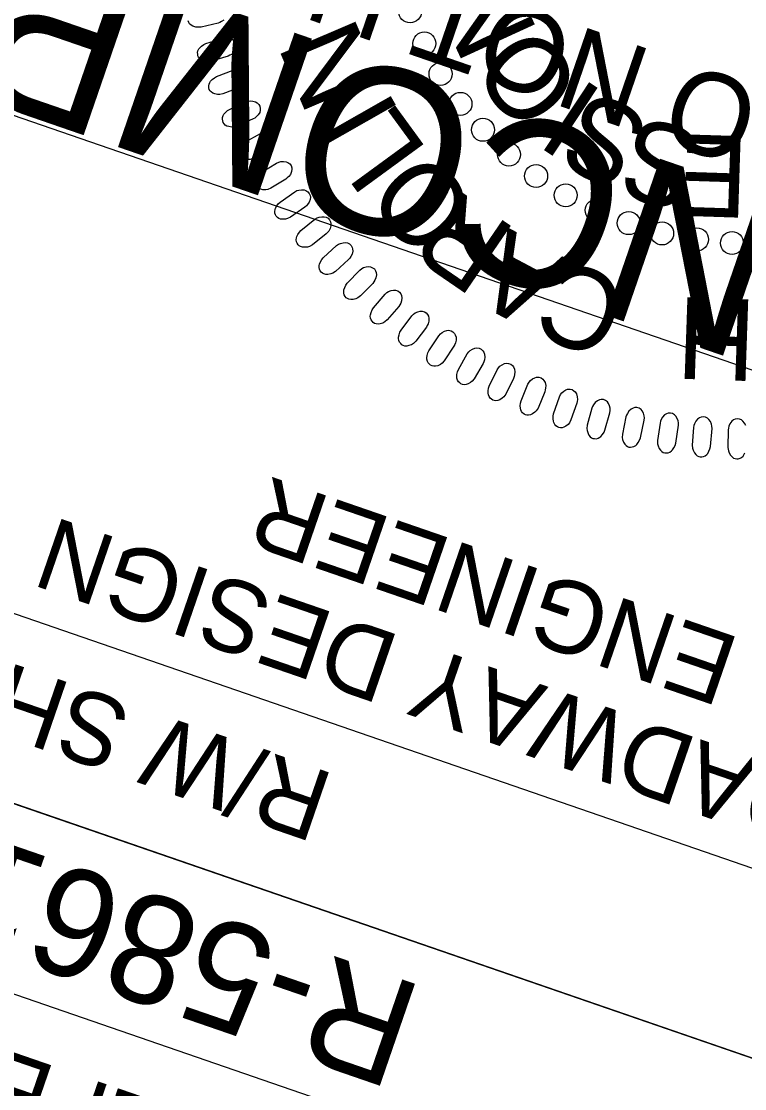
# Model space of a CAD drawing. Extents: x 479650 to 481768, y 492454 to 494037.
# Drawn here: x 479798.2 to 479848.6, y 492981.7 to 493055.9 of the extents above; entities that cross this region are included whole.
import ezdxf

# ---------------------------------------------------------------- set-up
doc = ezdxf.new("R2010")
doc.units = 0
for name, color, linetype in [('Sheet Data Field CELL', 7, 'Continuous'), ('Sheet PE Seal Cell', 7, 'Continuous'), ('Sheet Plan CELL', 7, 'Continuous'), ('Sheet Sticker Incomplete CELL', 7, 'Continuous')]:
    doc.layers.add(name, color=color, linetype=linetype)

msp = doc.modelspace()

# ---------------------------------------------------------------- linework, layer by layer
at = {"layer": 'Sheet PE Seal Cell'}
for points in [[(479812.334, 493055.999), (479812.174, 493055.892), (479812.055, 493055.833), (479811.933, 493055.789), (479810.739, 493055.505), (479810.517, 493055.49), (479810.369, 493055.509), (479810.178, 493055.578), (479810.049, 493055.648), (479809.946, 493055.738), (479809.882, 493055.831), (479809.837, 493055.935)], [(479848.654, 493027.806), (479848.568, 493027.968), (479848.458, 493028.109), (479848.362, 493028.191), (479848.206, 493028.253), (479848.057, 493028.276), (479847.907, 493028.239), (479847.801, 493028.191), (479847.673, 493028.094), (479847.55, 493027.926), (479847.48, 493027.748), (479847.447, 493027.619), (479847.43, 493027.489), (479847.408, 493026.263), (479847.441, 493026.043), (479847.491, 493025.903), (479847.6, 493025.731), (479847.695, 493025.619), (479847.806, 493025.538), (479847.91, 493025.496), (479848.022, 493025.474), (479848.135, 493025.491), (479848.254, 493025.52), (479848.36, 493025.577), (479848.467, 493025.675), (479848.528, 493025.754), (479848.598, 493025.902)]]:
    msp.add_lwpolyline(points, dxfattribs=at)
for points in [[(479812.623, 493053.492), (479811.45, 493053.135), (479811.229, 493053.106), (479811.08, 493053.115), (479810.885, 493053.173), (479810.752, 493053.234), (479810.643, 493053.318), (479810.574, 493053.406), (479810.522, 493053.508), (479810.509, 493053.621), (479810.503, 493053.744), (479810.529, 493053.861), (479810.594, 493053.991), (479810.653, 493054.071), (479810.777, 493054.179), (479810.931, 493054.289), (479811.076, 493054.357), (479812.276, 493054.731), (479812.445, 493054.759), (479812.592, 493054.757), (479812.77, 493054.718), (479812.937, 493054.651), (479813.041, 493054.581), (479813.144, 493054.449), (479813.207, 493054.311), (479813.213, 493054.157), (479813.195, 493054.042), (479813.137, 493053.891), (479813.01, 493053.728), (479812.858, 493053.611), (479812.742, 493053.544)], [(479813.41, 493051.294), (479812.262, 493050.862), (479812.043, 493050.821), (479811.893, 493050.82), (479811.696, 493050.866), (479811.558, 493050.918), (479811.445, 493050.995), (479811.371, 493051.079), (479811.312, 493051.177), (479811.292, 493051.289), (479811.278, 493051.412), (479811.297, 493051.531), (479811.354, 493051.664), (479811.407, 493051.748), (479811.524, 493051.863), (479811.671, 493051.982), (479811.812, 493052.059), (479812.986, 493052.508), (479813.153, 493052.546), (479813.299, 493052.553), (479813.48, 493052.525), (479813.65, 493052.47), (479813.759, 493052.407), (479813.871, 493052.281), (479813.941, 493052.148), (479813.956, 493051.994), (479813.947, 493051.879), (479813.898, 493051.724), (479813.781, 493051.553), (479813.637, 493051.427), (479813.526, 493051.353)], [(479814.365, 493049.117), (479813.246, 493048.615), (479813.031, 493048.56), (479812.882, 493048.55), (479812.681, 493048.583), (479812.542, 493048.626), (479812.423, 493048.696), (479812.343, 493048.775), (479812.279, 493048.869), (479812.252, 493048.98), (479812.23, 493049.101), (479812.241, 493049.221), (479812.289, 493049.358), (479812.338, 493049.445), (479812.447, 493049.567), (479812.586, 493049.695), (479812.722, 493049.782), (479813.866, 493050.302), (479814.03, 493050.352), (479814.176, 493050.368), (479814.357, 493050.351), (479814.531, 493050.306), (479814.644, 493050.25), (479814.763, 493050.132), (479814.842, 493050.003), (479814.867, 493049.851), (479814.864, 493049.735), (479814.826, 493049.578), (479814.72, 493049.399), (479814.583, 493049.264), (479814.477, 493049.184)], [(479815.463, 493046.948), (479814.377, 493046.377), (479814.166, 493046.307), (479814.018, 493046.288), (479813.815, 493046.309), (479813.673, 493046.344), (479813.55, 493046.405), (479813.466, 493046.479), (479813.396, 493046.57), (479813.362, 493046.678), (479813.333, 493046.798), (479813.336, 493046.918), (479813.376, 493047.057), (479813.419, 493047.148), (479813.52, 493047.277), (479813.651, 493047.413), (479813.781, 493047.507), (479814.89, 493048.099), (479815.05, 493048.159), (479815.195, 493048.184), (479815.378, 493048.179), (479815.553, 493048.145), (479815.67, 493048.096), (479815.796, 493047.985), (479815.883, 493047.862), (479815.917, 493047.711), (479815.922, 493047.596), (479815.893, 493047.437), (479815.799, 493047.252), (479815.671, 493047.109), (479815.57, 493047.022)], [(479816.645, 493044.94), (479815.597, 493044.301), (479815.391, 493044.219), (479815.244, 493044.191), (479815.041, 493044.198), (479814.897, 493044.224), (479814.77, 493044.278), (479814.682, 493044.346), (479814.606, 493044.433), (479814.565, 493044.538), (479814.528, 493044.656), (479814.525, 493044.776), (479814.555, 493044.918), (479814.592, 493045.01), (479814.686, 493045.145), (479814.807, 493045.29), (479814.931, 493045.393), (479816.001, 493046.053), (479816.157, 493046.122), (479816.3, 493046.156), (479816.482, 493046.163), (479816.661, 493046.14), (479816.779, 493046.099), (479816.912, 493045.996), (479817.007, 493045.878), (479817.051, 493045.73), (479817.063, 493045.615), (479817.043, 493045.454), (479816.961, 493045.264), (479816.842, 493045.113), (479816.747, 493045.02)], [(479817.974, 493042.984), (479816.969, 493042.281), (479816.768, 493042.185), (479816.623, 493042.148), (479816.42, 493042.143), (479816.275, 493042.159), (479816.145, 493042.205), (479816.052, 493042.269), (479815.971, 493042.349), (479815.924, 493042.452), (479815.88, 493042.567), (479815.869, 493042.687), (479815.891, 493042.83), (479815.921, 493042.925), (479816.006, 493043.066), (479816.118, 493043.218), (479816.237, 493043.328), (479817.262, 493044.054), (479817.414, 493044.133), (479817.554, 493044.176), (479817.736, 493044.194), (479817.915, 493044.183), (479818.036, 493044.148), (479818.175, 493044.054), (479818.277, 493043.943), (479818.33, 493043.798), (479818.349, 493043.683), (479818.34, 493043.522), (479818.27, 493043.327), (479818.161, 493043.169), (479818.072, 493043.07)], [(479819.45, 493041.128), (479818.491, 493040.364), (479818.297, 493040.256), (479818.155, 493040.21), (479817.952, 493040.192), (479817.806, 493040.199), (479817.674, 493040.237), (479817.578, 493040.294), (479817.492, 493040.37), (479817.437, 493040.469), (479817.387, 493040.582), (479817.368, 493040.701), (479817.38, 493040.845), (479817.406, 493040.941), (479817.481, 493041.088), (479817.584, 493041.246), (479817.694, 493041.363), (479818.672, 493042.152), (479818.819, 493042.24), (479818.956, 493042.292), (479819.137, 493042.322), (479819.315, 493042.321), (479819.439, 493042.295), (479819.584, 493042.21), (479819.692, 493042.105), (479819.754, 493041.964), (479819.78, 493041.85), (479819.782, 493041.689), (479819.724, 493041.49), (479819.625, 493041.325), (479819.542, 493041.221)], [(479821.01, 493039.337), (479820.101, 493038.514), (479819.914, 493038.395), (479819.775, 493038.339), (479819.574, 493038.309), (479819.428, 493038.307), (479819.293, 493038.337), (479819.193, 493038.387), (479819.103, 493038.457), (479819.043, 493038.554), (479818.985, 493038.663), (479818.959, 493038.78), (479818.962, 493038.925), (479818.981, 493039.022), (479819.046, 493039.173), (479819.14, 493039.338), (479819.243, 493039.462), (479820.169, 493040.311), (479820.31, 493040.408), (479820.444, 493040.468), (479820.622, 493040.509), (479820.801, 493040.52), (479820.925, 493040.501), (479821.075, 493040.425), (479821.19, 493040.328), (479821.261, 493040.19), (479821.294, 493040.079), (479821.306, 493039.917), (479821.26, 493039.715), (479821.172, 493039.545), (479821.096, 493039.435)], [(479822.688, 493037.686), (479821.832, 493036.807), (479821.652, 493036.676), (479821.517, 493036.612), (479821.319, 493036.569), (479821.173, 493036.558), (479821.037, 493036.579), (479820.934, 493036.623), (479820.839, 493036.687), (479820.773, 493036.78), (479820.708, 493036.885), (479820.675, 493037.001), (479820.67, 493037.145), (479820.682, 493037.244), (479820.739, 493037.398), (479820.821, 493037.568), (479820.916, 493037.699), (479821.787, 493038.604), (479821.921, 493038.71), (479822.051, 493038.779), (479822.227, 493038.831), (479822.405, 493038.852), (479822.53, 493038.842), (479822.684, 493038.775), (479822.805, 493038.685), (479822.884, 493038.552), (479822.924, 493038.444), (479822.946, 493038.283), (479822.913, 493038.079), (479822.837, 493037.903), (479822.767, 493037.79)], [(479824.502, 493036.073), (479823.704, 493035.142), (479823.532, 493035), (479823.402, 493034.927), (479823.206, 493034.872), (479823.061, 493034.852), (479822.924, 493034.864), (479822.819, 493034.902), (479822.72, 493034.96), (479822.649, 493035.048), (479822.577, 493035.149), (479822.537, 493035.262), (479822.522, 493035.406), (479822.529, 493035.506), (479822.575, 493035.663), (479822.646, 493035.838), (479822.733, 493035.974), (479823.546, 493036.933), (479823.674, 493037.046), (479823.799, 493037.123), (479823.97, 493037.186), (479824.147, 493037.219), (479824.272, 493037.216), (479824.43, 493037.159), (479824.557, 493037.077), (479824.644, 493036.95), (479824.691, 493036.844), (479824.723, 493036.685), (479824.703, 493036.479), (479824.637, 493036.298), (479824.575, 493036.181)], [(479826.422, 493034.634), (479825.683, 493033.655), (479825.521, 493033.502), (479825.395, 493033.422), (479825.203, 493033.354), (479825.06, 493033.325), (479824.922, 493033.329), (479824.815, 493033.36), (479824.713, 493033.412), (479824.636, 493033.495), (479824.558, 493033.592), (479824.51, 493033.702), (479824.487, 493033.844), (479824.488, 493033.944), (479824.524, 493034.104), (479824.584, 493034.283), (479824.662, 493034.425), (479825.413, 493035.432), (479825.533, 493035.554), (479825.653, 493035.639), (479825.821, 493035.712), (479825.995, 493035.755), (479826.12, 493035.761), (479826.282, 493035.714), (479826.413, 493035.64), (479826.508, 493035.518), (479826.562, 493035.415), (479826.603, 493035.259), (479826.597, 493035.052), (479826.542, 493034.868), (479826.488, 493034.746)], [(479828.346, 493033.313), (479827.671, 493032.289), (479827.519, 493032.127), (479827.398, 493032.039), (479827.211, 493031.959), (479827.07, 493031.921), (479826.932, 493031.916), (479826.823, 493031.941), (479826.718, 493031.986), (479826.635, 493032.064), (479826.552, 493032.155), (479826.498, 493032.262), (479826.466, 493032.403), (479826.459, 493032.503), (479826.486, 493032.665), (479826.535, 493032.848), (479826.603, 493032.994), (479827.29, 493034.046), (479827.402, 493034.175), (479827.517, 493034.267), (479827.679, 493034.351), (479827.85, 493034.405), (479827.975, 493034.419), (479828.139, 493034.382), (479828.274, 493034.316), (479828.377, 493034.2), (479828.437, 493034.101), (479828.488, 493033.948), (479828.495, 493033.741), (479828.452, 493033.554), (479828.406, 493033.43)], [(479830.372, 493032.114), (479829.761, 493031.05), (479829.62, 493030.878), (479829.505, 493030.783), (479829.323, 493030.692), (479829.185, 493030.645), (479829.048, 493030.632), (479828.937, 493030.649), (479828.83, 493030.687), (479828.743, 493030.76), (479828.654, 493030.846), (479828.593, 493030.95), (479828.552, 493031.089), (479828.539, 493031.187), (479828.555, 493031.351), (479828.592, 493031.536), (479828.653, 493031.686), (479829.271, 493032.78), (479829.375, 493032.915), (479829.483, 493033.014), (479829.641, 493033.108), (479829.807, 493033.173), (479829.931, 493033.194), (479830.097, 493033.168), (479830.237, 493033.111), (479830.347, 493033.002), (479830.412, 493032.907), (479830.473, 493032.757), (479830.492, 493032.551), (479830.462, 493032.362), (479830.423, 493032.234)], [(479832.49, 493031.081), (479831.948, 493029.981), (479831.817, 493029.8), (479831.709, 493029.699), (479831.533, 493029.596), (479831.397, 493029.54), (479831.262, 493029.519), (479831.15, 493029.529), (479831.041, 493029.56), (479830.949, 493029.628), (479830.855, 493029.708), (479830.788, 493029.808), (479830.738, 493029.944), (479830.719, 493030.041), (479830.725, 493030.206), (479830.751, 493030.393), (479830.801, 493030.546), (479831.35, 493031.676), (479831.445, 493031.818), (479831.547, 493031.924), (479831.698, 493032.027), (479831.86, 493032.103), (479831.982, 493032.132), (479832.15, 493032.116), (479832.293, 493032.068), (479832.409, 493031.966), (479832.481, 493031.875), (479832.552, 493031.729), (479832.584, 493031.524), (479832.564, 493031.334), (479832.534, 493031.204)], [(479834.667, 493030.146), (479834.195, 493029.014), (479834.076, 493028.825), (479833.974, 493028.717), (479833.805, 493028.603), (479833.673, 493028.54), (479833.539, 493028.509), (479833.427, 493028.513), (479833.316, 493028.538), (479833.22, 493028.599), (479833.121, 493028.673), (479833.047, 493028.768), (479832.989, 493028.9), (479832.965, 493028.997), (479832.96, 493029.161), (479832.974, 493029.35), (479833.014, 493029.505), (479833.492, 493030.668), (479833.577, 493030.816), (479833.672, 493030.928), (479833.817, 493031.04), (479833.974, 493031.126), (479834.094, 493031.163), (479834.262, 493031.157), (479834.408, 493031.119), (479834.531, 493031.024), (479834.608, 493030.937), (479834.687, 493030.796), (479834.732, 493030.594), (479834.725, 493030.403), (479834.703, 493030.271)], [(479836.889, 493029.353), (479836.489, 493028.193), (479836.382, 493027.998), (479836.286, 493027.882), (479836.125, 493027.759), (479835.997, 493027.687), (479835.866, 493027.648), (479835.754, 493027.644), (479835.641, 493027.662), (479835.542, 493027.718), (479835.438, 493027.785), (479835.359, 493027.875), (479835.293, 493028.004), (479835.262, 493028.099), (479835.247, 493028.262), (479835.249, 493028.452), (479835.28, 493028.61), (479835.683, 493029.8), (479835.759, 493029.953), (479835.847, 493030.07), (479835.984, 493030.192), (479836.136, 493030.288), (479836.253, 493030.331), (479836.422, 493030.336), (479836.569, 493030.306), (479836.697, 493030.22), (479836.78, 493030.139), (479836.868, 493030.003), (479836.925, 493029.804), (479836.931, 493029.612), (479836.916, 493029.48)], [(479837.946, 493028.998), (479837.619, 493027.815), (479837.597, 493027.594), (479837.611, 493027.446), (479837.674, 493027.252), (479837.738, 493027.12), (479837.825, 493027.014), (479837.915, 493026.947), (479838.018, 493026.898), (479838.131, 493026.888), (479838.254, 493026.885), (479838.371, 493026.914), (479838.499, 493026.983), (479838.577, 493027.044), (479838.682, 493027.17), (479838.788, 493027.327), (479838.852, 493027.475), (479839.193, 493028.685), (479839.217, 493028.854), (479839.21, 493029), (479839.167, 493029.178), (479839.095, 493029.342), (479839.024, 493029.445), (479838.888, 493029.545), (479838.749, 493029.604), (479838.594, 493029.605), (479838.48, 493029.585), (479838.331, 493029.522), (479838.171, 493029.391), (479838.058, 493029.235), (479837.994, 493029.119)], [(479840.317, 493028.395), (479840.066, 493027.194), (479840.057, 493026.972), (479840.08, 493026.825), (479840.155, 493026.636), (479840.228, 493026.508), (479840.321, 493026.407), (479840.415, 493026.347), (479840.521, 493026.304), (479840.635, 493026.301), (479840.758, 493026.306), (479840.872, 493026.343), (479840.996, 493026.419), (479841.07, 493026.485), (479841.167, 493026.617), (479841.262, 493026.781), (479841.317, 493026.932), (479841.581, 493028.161), (479841.595, 493028.331), (479841.579, 493028.477), (479841.524, 493028.652), (479841.443, 493028.811), (479841.364, 493028.909), (479841.223, 493029), (479841.081, 493029.051), (479840.926, 493029.042), (479840.813, 493029.014), (479840.669, 493028.943), (479840.517, 493028.802), (479840.415, 493028.64), (479840.359, 493028.519)], [(479842.688, 493027.967), (479842.513, 493026.754), (479842.518, 493026.531), (479842.55, 493026.385), (479842.637, 493026.201), (479842.717, 493026.079), (479842.816, 493025.984), (479842.914, 493025.93), (479843.023, 493025.893), (479843.137, 493025.897), (479843.259, 493025.91), (479843.371, 493025.954), (479843.49, 493026.038), (479843.56, 493026.108), (479843.648, 493026.247), (479843.733, 493026.416), (479843.778, 493026.57), (479843.965, 493027.813), (479843.967, 493027.984), (479843.943, 493028.129), (479843.877, 493028.299), (479843.786, 493028.454), (479843.701, 493028.547), (479843.554, 493028.628), (479843.409, 493028.669), (479843.255, 493028.651), (479843.145, 493028.617), (479843.005, 493028.536), (479842.862, 493028.386), (479842.77, 493028.218), (479842.722, 493028.094)], [(479845.022, 493027.663), (479844.923, 493026.44), (479844.942, 493026.219), (479844.983, 493026.075), (479845.081, 493025.897), (479845.169, 493025.78), (479845.274, 493025.691), (479845.376, 493025.642), (479845.486, 493025.614), (479845.599, 493025.624), (479845.721, 493025.645), (479845.83, 493025.696), (479845.942, 493025.787), (479846.008, 493025.862), (479846.088, 493026.006), (479846.161, 493026.18), (479846.197, 493026.337), (479846.306, 493027.589), (479846.297, 493027.759), (479846.263, 493027.902), (479846.187, 493028.069), (479846.087, 493028.217), (479845.996, 493028.304), (479845.844, 493028.377), (479845.697, 493028.409), (479845.545, 493028.381), (479845.437, 493028.34), (479845.302, 493028.25), (479845.169, 493028.091), (479845.087, 493027.917), (479845.047, 493027.791)]]:
    msp.add_lwpolyline(points, close=True, dxfattribs=at)
for centre in [(479825.289, 493056.604), (479826.285, 493054.364), (479827.409, 493052.249), (479828.797, 493050.168), (479830.364, 493048.364), (479832.172, 493046.645), (479834.058, 493045.151), (479836.121, 493043.808), (479838.288, 493042.765), (479840.508, 493041.873), (479842.829, 493041.157), (479845.255, 493040.742), (479847.695, 493040.49)]:
    msp.add_circle(centre, 0.801, dxfattribs=at)
at = {"layer": 'Sheet Plan CELL'}
for p, q in [((479871.047, 492976.253), (479681.911, 493041.391)), ((479871.047, 492976.253), (479681.911, 493041.391)), ((479866.974, 492964.395), (479677.84, 493029.572))]:
    msp.add_line(p, q, dxfattribs=at)
for points in [[(479875.114, 492988.059), (479780.521, 493020.65), (479817.172, 493127.026), (479911.745, 493094.415)], [(479862.874, 492952.534), (479673.716, 493017.719), (479681.911, 493041.391), (479871.047, 492976.253)]]:
    msp.add_lwpolyline(points, close=True, dxfattribs=at)
at = {"layer": 'Sheet Sticker Incomplete CELL'}
msp.add_lwpolyline([(479868.336, 493049.89), (479860.681, 493027.672), (479721.698, 493075.556), (479729.353, 493097.774)], close=True, dxfattribs=at)

# ---------------------------------------------------------------- texts
at = {"layer": 'Sheet Data Field CELL'}
msp.add_text('R-5861', height=7.5, rotation=160.98924, dxfattribs=at).set_placement((479826.407, 492988.711))
at = {"layer": 'Sheet PE Seal Cell'}
for s, rotation, p in [('N', 114.63949, (479834.23, 493055.129)), ('N', 113.15142, (479823.398, 493051.417)), ('O', 130.51908, (479837.556, 493051.546)), ('I', 146.39868, (479838.922, 493050.894)), ('I', 119.64078, (479824.641, 493049.486)), ('S', 154.33847, (479842.309, 493049.059)), ('L', 126.13013, (479826.584, 493046.857)), ('S', 162.27827, (479845.992, 493047.897)), ('E', 178.15786, (479848.921, 493047.903)), ('O', 132.61949, (479830.234, 493042.922)), ('R', 145.5982, (479832.815, 493041.341)), ('A', 152.08756, (479836.533, 493039.22)), ('C', 158.57692, (479840.791, 493037.533)), ('H', 178.04499, (479849.446, 493036.543))]:
    msp.add_text(s, height=5.669, rotation=rotation, dxfattribs=at).set_placement(p)
at = {"layer": 'Sheet Plan CELL'}
for s, p in [('ENGINEER', (479848.405, 493012.955)), ('ROADWAY DESIGN', (479859.174, 493001.272)), ('R/W SHEET NO.', (479820.148, 493003.507)), ('PROJECT REFERENCE NO.', (479844.727, 492968.014))]:
    msp.add_text(s, height=5.0001, rotation=160.98924, dxfattribs=at).set_placement(p)
at = {"layer": 'Sheet Sticker Incomplete CELL'}
for s, height, p in [('DO NOT USE FOR R/W ACQUISITION', 5.76, (479855.254, 493049.373)), ('INCOMPLETE PLANS', 11.52, (479856.063, 493041.743))]:
    msp.add_text(s, height=height, rotation=160.98924, dxfattribs=at).set_placement(p)

doc.saveas('drawing.dxf')
